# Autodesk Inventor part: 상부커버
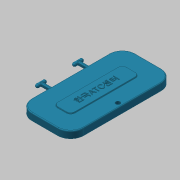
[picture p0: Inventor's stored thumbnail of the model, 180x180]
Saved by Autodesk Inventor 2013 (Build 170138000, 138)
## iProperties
Created: 2016-02
Part Number: 상부커버
Material: ABS 플라스틱
Document SubType Name: Modeling
Designer: mduedu
Density: 2.71 g/cm^3
Mass: 42.0587 g
Surface Area: 149.263 cm^2
Volume: 15.5198 cm^3
Author: mduedu
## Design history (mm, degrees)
sketch "스케치1"
  geometry: L1 (30, 60)-(-30, 60); L2 (-30, 60)-(-30, -60); L3 (-30, -60)-(30, -60); L4 (30, -60)-(30, 60); L5 (30, 60)-(-30, -60); L6 (-30, 60)-(30, -60); 1 further point
  constraints: 12 end point, 2 midpoint, 2 parallel, 1 horizontal, 1 perpendicular
  dimensions: "d0" = 60 distance of L2.end L3.end; "d2" = 120 distance of L1.end L2.end
extrude "돌출1" new body sketch "스케치1" distance "d3" = 8; taper "d4" = 0 deg
fillet "모깎기1" dims "d5" = 15
node "작업 평면1"
sketch "스케치7"
  geometry: L1 (-39, 4)-(129, 4) reference; L2 (65, 2)-(68, 2); L3 (68, 2)-(68, 6); L4 (68, 6)-(65, 6); L5 (65, 6)-(65, 2); L6 (65, 2)-(68, 6); L7 (68, 2)-(65, 6); 2 further points
  constraints: 12 end point, 2 midpoint, 2 parallel, 1 horizontal, 1 perpendicular, 1 point on line
  dimensions: "d33" = 4 distance of L2.end L3.end; "d35" = 3 distance of L3.end L4.end; "d36" = 20 distance from line of L5 point (45, 0)
extrude "돌출3" join sketch "스케치7" distance "d37" = 15; taper "d38" = 0 deg
fillet "모깎기6" dims "d39" = 2
node "작업 평면3"
sketch "스케치8"
  geometry: A1 r 2 centre (-13, 2) between (-13, 4) and (-13, 0) reference; 2 further points
  constraints: 1 coincident, 1 vertical alignment, 2 other
extrude "돌출4" join sketch "스케치8" stored distance "d40" = 12; taper "d41" = 0 deg
fillet "모깎기7" dims "d42" = 2
fillet "모깎기8" dims "d43" = 1
fillet "모깎기9" dims "d44" = 1
sketch "스케치2"
  geometry: L1 (30, 45)-(30, -45) reference; L2 (15, -60)-(-15, -60) reference; L3 (-30, -45)-(-30, 45) reference; L4 (-15, 60)-(15, 60) reference; L5 (25, 45)-(25, -45); L6 (15, -55)-(-15, -55); L7 (-25, -45)-(-25, 45); L8 (-15, 55)-(15, 55); A1 r 15 centre (15, 45) between (30, 45) and (15, 60) reference; A2 r 15 centre (15, -45) between (15, -60) and (30, -45) reference; A3 r 15 centre (-15, -45) between (-30, -45) and (-15, -60) reference; A4 r 15 centre (-15, 45) between (-15, 60) and (-30, 45) reference; A5 r 10 centre (15, 45) between (25, 45) and (15, 55); A6 r 10 centre (15, -45) between (15, -55) and (25, -45); A7 r 10 centre (-15, -45) between (-25, -45) and (-15, -55); A8 r 10 centre (-15, 45) between (-15, 55) and (-25, 45); 4 further points
  constraints: 8 end point, 8 point on circle, 4 centre point, 4 midpoint, 7 other
  dimensions: "d8" = 5 distance between parallel lines of L7 L3
hole "구멍1" sketch "스케치2" at (25, 0) diameter "d9" = 5; stored, may be unused: countersink angle "d13" = 90 deg, drill point angle "d15" = 118 deg; dims "d10" = 6, "d11" = 4, "d12" = 2, "d14" = 8
sketch "스케치3"
  geometry: L1 (10, -40)-(-10, -40); L2 (-10, -40)-(-10, 40); L3 (-10, 40)-(10, 40); L4 (10, 40)-(10, -40); L5 (10, -40)-(-10, 40); L6 (-10, -40)-(10, 40); 1 further point
  constraints: 12 end point, 2 midpoint, 2 parallel, 1 horizontal, 1 perpendicular
  dimensions: "d16" = 80 distance of L1.end L2.end; "d18" = 20 distance of L2.end L3.end
extrude "돌출2" join sketch "스케치3" distance "d19" = 1; taper "d20" = 0 deg
fillet "모깎기2" dims "d21" = 5
fillet "모깎기3" dims "d22" = 0.3
sketch "스케치4"
  geometry: 2 further points
  constraints: 1 coincident, 1 other
feature "엠보싱1" sketch "스케치4" dims "d8" = 5, "d24" = 0.5, "d25" = 0
fillet "모깎기10" dims "d45" = 1
node "솔리드1"
mirror "대칭1"
node "절단 모서리 투영1"
